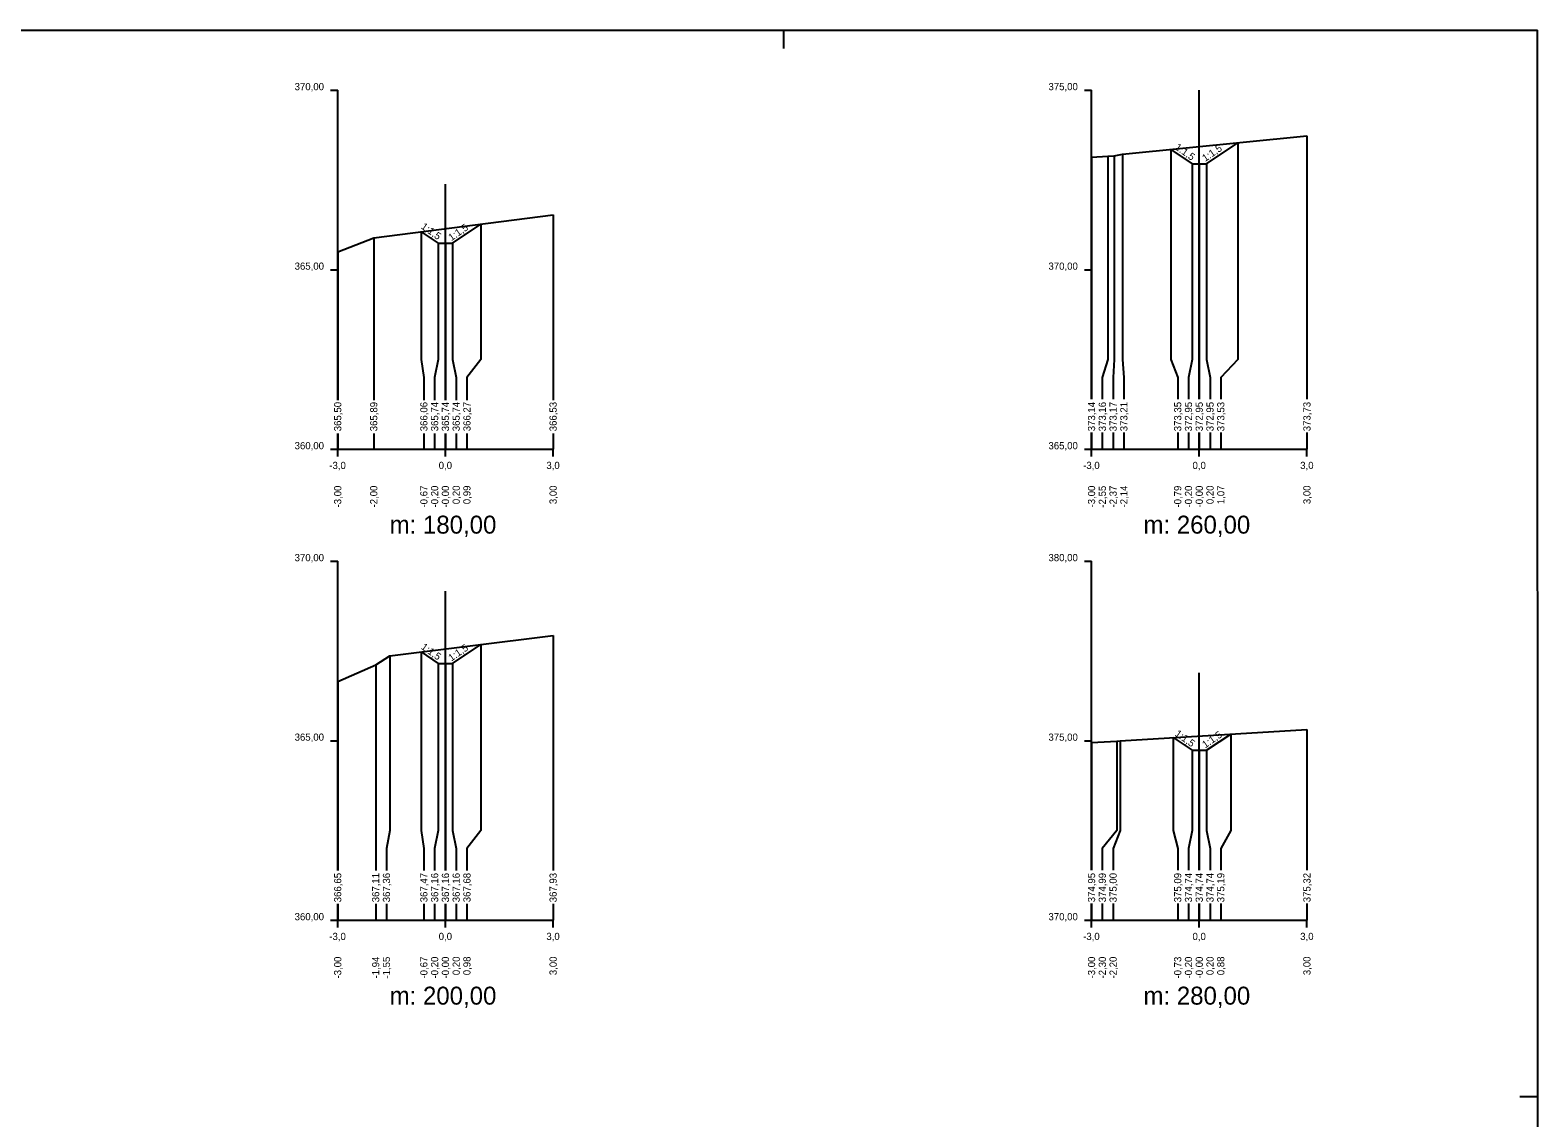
# Model space of a CAD drawing. Extents: x -497367.2 to -497283.2, y -1136708.7 to -1136649.3.
# Drawn here: x -497325.24 to -497283.24, y -1136679.63 to -1136649.33 of the extents above; entities that cross this region are included whole.
import ezdxf

# ---------------------------------------------------------------- set-up
doc = ezdxf.new("R2010")
doc.units = 0
for name, color, linetype in [('11', 7, 'Continuous'), ('16', 7, 'Continuous'), ('21', 7, 'Continuous'), ('28', 7, 'Continuous'), ('59', 7, 'Continuous'), ('8', 7, 'Continuous'), ('Vrstva 63', 7, 'Continuous')]:
    doc.layers.add(name, color=color, linetype=linetype)

msp = doc.modelspace()

# ---------------------------------------------------------------- linework, layer by layer
for points in [[(-497295.671, -1136652.867), (-497295.22, -1136652.847), (-497295.042, -1136652.833), (-497294.809, -1136652.792), (-497289.671, -1136652.279)], [(-497293.464, -1136652.658), (-497292.871, -1136653.053), (-497292.671, -1136653.053), (-497292.471, -1136653.053), (-497291.598, -1136652.472)], [(-497291.598, -1136652.473), (-497291.598, -1136652.472), (-497291.598, -1136652.471)], [(-497292.871, -1136653.054), (-497292.871, -1136653.053), (-497292.871, -1136653.052)], [(-497292.471, -1136653.054), (-497292.471, -1136653.053), (-497292.471, -1136653.052)], [(-497316.671, -1136655.507), (-497315.668, -1136655.115), (-497310.671, -1136654.48)], [(-497314.344, -1136654.946), (-497313.871, -1136655.262), (-497313.671, -1136655.262), (-497313.471, -1136655.262), (-497312.68, -1136654.735)], [(-497313.871, -1136655.263), (-497313.871, -1136655.262), (-497313.871, -1136655.261)], [(-497313.471, -1136655.263), (-497313.471, -1136655.262), (-497313.471, -1136655.261)], [(-497316.671, -1136667.479), (-497315.613, -1136667.015), (-497315.221, -1136666.762), (-497310.671, -1136666.198)], [(-497314.346, -1136666.653), (-497313.871, -1136666.97), (-497313.671, -1136666.97), (-497313.471, -1136666.97), (-497312.688, -1136666.448)], [(-497313.871, -1136666.971), (-497313.871, -1136666.97), (-497313.871, -1136666.969)], [(-497313.471, -1136666.971), (-497313.471, -1136666.97), (-497313.471, -1136666.969)], [(-497295.671, -1136669.172), (-497294.97, -1136669.134), (-497294.875, -1136669.128), (-497289.671, -1136668.808)], [(-497293.399, -1136669.037), (-497292.871, -1136669.389), (-497292.671, -1136669.389), (-497292.471, -1136669.389), (-497291.795, -1136668.939)], [(-497292.871, -1136669.39), (-497292.871, -1136669.389), (-497292.871, -1136669.388)], [(-497292.471, -1136669.39), (-497292.471, -1136669.389), (-497292.471, -1136669.388)]]:
    msp.add_lwpolyline(points)
at = {"layer": '11'}
for points in [[(-497291.598, -1136652.472), (-497291.598, -1136658.506), (-497292.071, -1136659.006), (-497292.071, -1136659.608)], [(-497289.671, -1136652.279), (-497289.671, -1136658.506), (-497289.671, -1136659.006), (-497289.671, -1136659.608)], [(-497295.671, -1136652.867), (-497295.671, -1136658.506), (-497295.671, -1136659.006), (-497295.671, -1136659.608)], [(-497295.22, -1136652.847), (-497295.22, -1136658.506), (-497295.371, -1136659.006), (-497295.371, -1136659.608)], [(-497295.042, -1136652.833), (-497295.042, -1136658.506), (-497295.071, -1136659.006), (-497295.071, -1136659.608)], [(-497294.809, -1136652.792), (-497294.809, -1136658.506), (-497294.771, -1136659.006), (-497294.771, -1136659.608)], [(-497293.464, -1136652.658), (-497293.464, -1136658.506), (-497293.271, -1136659.006), (-497293.271, -1136659.608)], [(-497292.871, -1136653.053), (-497292.871, -1136658.506), (-497292.971, -1136659.006), (-497292.971, -1136659.608)], [(-497292.671, -1136653.053), (-497292.671, -1136658.506), (-497292.671, -1136659.006), (-497292.671, -1136659.608)], [(-497292.471, -1136653.053), (-497292.471, -1136658.506), (-497292.371, -1136659.006), (-497292.371, -1136659.608)], [(-497310.671, -1136654.48), (-497310.671, -1136658.506), (-497310.671, -1136659.006), (-497310.671, -1136659.635)], [(-497315.668, -1136655.115), (-497315.668, -1136658.506), (-497315.668, -1136659.006), (-497315.668, -1136659.635)], [(-497314.344, -1136654.946), (-497314.344, -1136658.506), (-497314.271, -1136659.006), (-497314.271, -1136659.635)], [(-497312.68, -1136654.735), (-497312.68, -1136658.506), (-497313.071, -1136659.006), (-497313.071, -1136659.635)], [(-497316.671, -1136655.507), (-497316.671, -1136658.506), (-497316.671, -1136659.006), (-497316.671, -1136659.635)], [(-497313.871, -1136655.262), (-497313.871, -1136658.506), (-497313.971, -1136659.006), (-497313.971, -1136659.635)], [(-497313.671, -1136655.262), (-497313.671, -1136658.506), (-497313.671, -1136659.006), (-497313.671, -1136659.635)], [(-497313.471, -1136655.262), (-497313.471, -1136658.506), (-497313.371, -1136659.006), (-497313.371, -1136659.635)], [(-497316.671, -1136660.569), (-497316.671, -1136661.006)], [(-497315.668, -1136660.569), (-497315.668, -1136661.006)], [(-497314.271, -1136660.569), (-497314.271, -1136661.006)], [(-497313.971, -1136660.569), (-497313.971, -1136661.006)], [(-497313.671, -1136660.569), (-497313.671, -1136661.006)], [(-497313.371, -1136660.569), (-497313.371, -1136661.006)], [(-497313.071, -1136660.569), (-497313.071, -1136661.006)], [(-497310.671, -1136660.569), (-497310.671, -1136661.006)], [(-497295.671, -1136660.542), (-497295.671, -1136661.006)], [(-497295.371, -1136660.542), (-497295.371, -1136661.006)], [(-497295.071, -1136660.542), (-497295.071, -1136661.006)], [(-497294.771, -1136660.542), (-497294.771, -1136661.006)], [(-497293.271, -1136660.542), (-497293.271, -1136661.006)], [(-497292.971, -1136660.542), (-497292.971, -1136661.006)], [(-497292.671, -1136660.542), (-497292.671, -1136661.006)], [(-497292.371, -1136660.542), (-497292.371, -1136661.006)], [(-497292.071, -1136660.542), (-497292.071, -1136661.006)], [(-497289.671, -1136660.542), (-497289.671, -1136661.006)], [(-497312.688, -1136666.448), (-497312.688, -1136671.625), (-497313.071, -1136672.125), (-497313.071, -1136672.738)], [(-497310.671, -1136666.198), (-497310.671, -1136671.625), (-497310.671, -1136672.125), (-497310.671, -1136672.738)], [(-497315.221, -1136666.762), (-497315.221, -1136671.625), (-497315.313, -1136672.125), (-497315.313, -1136672.738)], [(-497314.346, -1136666.653), (-497314.346, -1136671.625), (-497314.271, -1136672.125), (-497314.271, -1136672.738)], [(-497315.613, -1136667.015), (-497315.613, -1136671.625), (-497315.613, -1136672.125), (-497315.613, -1136672.738)], [(-497313.871, -1136666.97), (-497313.871, -1136671.625), (-497313.971, -1136672.125), (-497313.971, -1136672.738)], [(-497313.671, -1136666.97), (-497313.671, -1136671.625), (-497313.671, -1136672.125), (-497313.671, -1136672.738)], [(-497313.471, -1136666.97), (-497313.471, -1136671.625), (-497313.371, -1136672.125), (-497313.371, -1136672.738)], [(-497316.671, -1136667.479), (-497316.671, -1136671.625), (-497316.671, -1136672.125), (-497316.671, -1136672.738)], [(-497291.795, -1136668.939), (-497291.795, -1136671.625), (-497292.071, -1136672.125), (-497292.071, -1136672.728)], [(-497289.671, -1136668.808), (-497289.671, -1136671.625), (-497289.671, -1136672.125), (-497289.671, -1136672.728)], [(-497295.671, -1136669.172), (-497295.671, -1136671.625), (-497295.671, -1136672.125), (-497295.671, -1136672.728)], [(-497294.97, -1136669.134), (-497294.97, -1136671.625), (-497295.371, -1136672.125), (-497295.371, -1136672.728)], [(-497294.875, -1136669.128), (-497294.875, -1136671.625), (-497295.071, -1136672.125), (-497295.071, -1136672.728)], [(-497293.399, -1136669.037), (-497293.399, -1136671.625), (-497293.271, -1136672.125), (-497293.271, -1136672.728)], [(-497292.871, -1136669.389), (-497292.871, -1136671.625), (-497292.971, -1136672.125), (-497292.971, -1136672.728)], [(-497292.671, -1136669.389), (-497292.671, -1136671.625), (-497292.671, -1136672.125), (-497292.671, -1136672.728)], [(-497292.471, -1136669.389), (-497292.471, -1136671.625), (-497292.371, -1136672.125), (-497292.371, -1136672.728)], [(-497316.671, -1136673.672), (-497316.671, -1136674.125)], [(-497315.613, -1136673.672), (-497315.613, -1136674.125)], [(-497315.313, -1136673.672), (-497315.313, -1136674.125)], [(-497314.271, -1136673.672), (-497314.271, -1136674.125)], [(-497313.971, -1136673.672), (-497313.971, -1136674.125)], [(-497313.671, -1136673.672), (-497313.671, -1136674.125)], [(-497313.371, -1136673.672), (-497313.371, -1136674.125)], [(-497313.071, -1136673.672), (-497313.071, -1136674.125)], [(-497310.671, -1136673.672), (-497310.671, -1136674.125)], [(-497295.671, -1136673.662), (-497295.671, -1136674.125)], [(-497295.371, -1136673.662), (-497295.371, -1136674.125)], [(-497295.071, -1136673.662), (-497295.071, -1136674.125)], [(-497293.271, -1136673.662), (-497293.271, -1136674.125)], [(-497292.971, -1136673.662), (-497292.971, -1136674.125)], [(-497292.671, -1136673.662), (-497292.671, -1136674.125)], [(-497292.371, -1136673.662), (-497292.371, -1136674.125)], [(-497292.071, -1136673.662), (-497292.071, -1136674.125)], [(-497289.671, -1136673.662), (-497289.671, -1136674.125)]]:
    msp.add_lwpolyline(points, dxfattribs=at)
at = {"layer": '16'}
for p, q in [((-497316.671, -1136661.006), (-497310.671, -1136661.006)), ((-497295.671, -1136661.006), (-497289.671, -1136661.006)), ((-497316.671, -1136674.125), (-497310.671, -1136674.125)), ((-497295.671, -1136674.125), (-497289.671, -1136674.125))]:
    msp.add_line(p, q, dxfattribs=at)
for points in [[(-497292.671, -1136653.054), (-497292.671, -1136653.053), (-497292.671, -1136653.052)], [(-497313.671, -1136655.262), (-497313.671, -1136655.262), (-497313.671, -1136655.261)], [(-497313.671, -1136666.971), (-497313.671, -1136666.97), (-497313.671, -1136666.969)], [(-497292.671, -1136669.39), (-497292.671, -1136669.389), (-497292.671, -1136669.388)]]:
    msp.add_lwpolyline(points, dxfattribs=at)
at = {"layer": '21'}
for p, q in [((-497316.871, -1136651.006), (-497316.671, -1136651.006)), ((-497295.871, -1136651.006), (-497295.671, -1136651.006)), ((-497316.871, -1136656.006), (-497316.671, -1136656.006)), ((-497295.871, -1136656.006), (-497295.671, -1136656.006)), ((-497316.871, -1136661.006), (-497316.671, -1136661.006)), ((-497295.871, -1136661.006), (-497295.671, -1136661.006)), ((-497316.871, -1136664.125), (-497316.671, -1136664.125)), ((-497295.871, -1136664.125), (-497295.671, -1136664.125)), ((-497316.871, -1136669.125), (-497316.671, -1136669.125)), ((-497295.871, -1136669.125), (-497295.671, -1136669.125)), ((-497316.871, -1136674.125), (-497316.671, -1136674.125)), ((-497295.871, -1136674.125), (-497295.671, -1136674.125))]:
    msp.add_line(p, q, dxfattribs=at)
at = {"layer": '28'}
for p, q in [((-497292.671, -1136659.608), (-497292.671, -1136651.006)), ((-497313.671, -1136659.635), (-497313.671, -1136653.627)), ((-497313.671, -1136661.006), (-497313.671, -1136660.569)), ((-497292.671, -1136661.006), (-497292.671, -1136660.542)), ((-497313.671, -1136672.738), (-497313.671, -1136664.955)), ((-497292.671, -1136672.728), (-497292.671, -1136667.233)), ((-497313.671, -1136674.125), (-497313.671, -1136673.672)), ((-497292.671, -1136674.125), (-497292.671, -1136673.662))]:
    msp.add_line(p, q, dxfattribs=at)
at = {"layer": '59'}
for p, q in [((-497316.671, -1136661.206), (-497316.671, -1136661.006)), ((-497313.671, -1136661.206), (-497313.671, -1136661.006)), ((-497310.671, -1136661.206), (-497310.671, -1136661.006)), ((-497295.671, -1136661.206), (-497295.671, -1136661.006)), ((-497292.671, -1136661.206), (-497292.671, -1136661.006)), ((-497289.671, -1136661.206), (-497289.671, -1136661.006)), ((-497316.671, -1136674.325), (-497316.671, -1136674.125)), ((-497313.671, -1136674.325), (-497313.671, -1136674.125)), ((-497310.671, -1136674.325), (-497310.671, -1136674.125)), ((-497295.671, -1136674.325), (-497295.671, -1136674.125)), ((-497292.671, -1136674.325), (-497292.671, -1136674.125)), ((-497289.671, -1136674.325), (-497289.671, -1136674.125))]:
    msp.add_line(p, q, dxfattribs=at)
at = {"layer": '8'}
for p, q in [((-497316.671, -1136659.635), (-497316.671, -1136651.006)), ((-497295.671, -1136659.608), (-497295.671, -1136651.006)), ((-497316.671, -1136661.006), (-497316.671, -1136660.569)), ((-497295.671, -1136661.006), (-497295.671, -1136660.542)), ((-497316.671, -1136672.738), (-497316.671, -1136664.125)), ((-497295.671, -1136672.728), (-497295.671, -1136664.125)), ((-497316.671, -1136674.125), (-497316.671, -1136673.672)), ((-497295.671, -1136674.125), (-497295.671, -1136673.662))]:
    msp.add_line(p, q, dxfattribs=at)
at = {"layer": 'Vrstva 63'}
for p, q in [((-497367.248, -1136649.335), (-497283.248, -1136649.333)), ((-497304.239, -1136649.84), (-497304.239, -1136649.337)), ((-497283.238, -1136708.735), (-497283.248, -1136649.333)), ((-497283.743, -1136679.034), (-497283.243, -1136679.034))]:
    msp.add_line(p, q, dxfattribs=at)

# ---------------------------------------------------------------- texts
at = {"layer": '16'}
for s, p in [('365,50', (-497316.571, -1136660.506)), ('365,89', (-497315.568, -1136660.506)), ('366,06', (-497314.171, -1136660.506)), ('365,74', (-497313.871, -1136660.506)), ('365,74', (-497313.571, -1136660.506)), ('365,74', (-497313.271, -1136660.506)), ('366,27', (-497312.971, -1136660.506)), ('366,53', (-497310.571, -1136660.506)), ('373,14', (-497295.571, -1136660.506)), ('373,16', (-497295.271, -1136660.506)), ('373,17', (-497294.971, -1136660.506)), ('373,21', (-497294.671, -1136660.506)), ('373,35', (-497293.171, -1136660.506)), ('372,95', (-497292.871, -1136660.506)), ('372,95', (-497292.571, -1136660.506)), ('372,95', (-497292.271, -1136660.506)), ('373,53', (-497291.971, -1136660.506)), ('373,73', (-497289.571, -1136660.506)), ('366,65', (-497316.571, -1136673.625)), ('367,11', (-497315.513, -1136673.625)), ('367,36', (-497315.213, -1136673.625)), ('367,47', (-497314.171, -1136673.625)), ('367,16', (-497313.871, -1136673.625)), ('367,16', (-497313.571, -1136673.625)), ('367,16', (-497313.271, -1136673.625)), ('367,68', (-497312.971, -1136673.625)), ('367,93', (-497310.571, -1136673.625)), ('374,95', (-497295.571, -1136673.625)), ('374,99', (-497295.271, -1136673.625)), ('375,00', (-497294.971, -1136673.625)), ('375,09', (-497293.171, -1136673.625)), ('374,74', (-497292.871, -1136673.625)), ('374,74', (-497292.571, -1136673.625)), ('374,74', (-497292.271, -1136673.625)), ('375,19', (-497291.971, -1136673.625)), ('375,32', (-497289.571, -1136673.625))]:
    msp.add_text(s, height=0.2, rotation=90, dxfattribs=at).set_placement(p)
at = {"layer": '21'}
for s, p in [('370,00', (-497317.871, -1136651.006)), ('375,00', (-497296.871, -1136651.006)), ('365,00', (-497317.871, -1136656.006)), ('370,00', (-497296.871, -1136656.006)), ('360,00', (-497317.871, -1136661.006)), ('365,00', (-497296.871, -1136661.006)), ('-3,0', (-497316.905, -1136661.556)), ('0,0', (-497313.858, -1136661.556)), ('3,0', (-497310.858, -1136661.556)), ('-3,0', (-497295.905, -1136661.556)), ('0,0', (-497292.858, -1136661.556)), ('3,0', (-497289.858, -1136661.556)), ('370,00', (-497317.871, -1136664.125)), ('380,00', (-497296.871, -1136664.125)), ('365,00', (-497317.871, -1136669.125)), ('375,00', (-497296.871, -1136669.125)), ('360,00', (-497317.871, -1136674.125)), ('370,00', (-497296.871, -1136674.125)), ('-3,0', (-497316.905, -1136674.675)), ('0,0', (-497313.858, -1136674.675)), ('3,0', (-497310.858, -1136674.675)), ('-3,0', (-497295.905, -1136674.675)), ('0,0', (-497292.858, -1136674.675)), ('3,0', (-497289.858, -1136674.675))]:
    msp.add_text(s, height=0.2, dxfattribs=at).set_placement(p)
for rotation, p in [(324.91, (-497293.367, -1136652.635)), (34.4489, (-497292.504, -1136653.005)), (324.91, (-497314.367, -1136654.843)), (34.4489, (-497313.504, -1136655.213)), (324.91, (-497314.367, -1136666.552)), (34.4489, (-497313.504, -1136666.921)), (324.91, (-497293.367, -1136668.971)), (34.4489, (-497292.504, -1136669.341))]:
    msp.add_text('1:1,5', height=0.2, rotation=rotation, dxfattribs=at).set_placement(p)
at = {"layer": '28'}
for s, p in [('m: 180,00', (-497315.224, -1136663.356)), ('m: 260,00', (-497294.224, -1136663.356)), ('m: 200,00', (-497315.224, -1136676.475)), ('m: 280,00', (-497294.224, -1136676.475))]:
    msp.add_text(s, height=0.5, dxfattribs=at).set_placement(p)
at = {"layer": '59'}
for s, p in [('-3,00', (-497316.571, -1136662.629)), ('-2,00', (-497315.568, -1136662.629)), ('-0,67', (-497314.171, -1136662.63)), ('-0,20', (-497313.871, -1136662.629)), ('-0,00', (-497313.571, -1136662.629)), ('0,20', (-497313.271, -1136662.536)), ('0,99', (-497312.971, -1136662.537)), ('3,00', (-497310.571, -1136662.536)), ('-3,00', (-497295.571, -1136662.629)), ('-2,55', (-497295.271, -1136662.632)), ('-2,37', (-497294.971, -1136662.63)), ('-2,14', (-497294.671, -1136662.629)), ('-0,79', (-497293.171, -1136662.63)), ('-0,20', (-497292.871, -1136662.629)), ('-0,00', (-497292.571, -1136662.629)), ('0,20', (-497292.271, -1136662.536)), ('1,07', (-497291.971, -1136662.537)), ('3,00', (-497289.571, -1136662.536)), ('-3,00', (-497316.571, -1136675.748)), ('-1,94', (-497315.513, -1136675.748)), ('-1,55', (-497315.213, -1136675.75)), ('-0,67', (-497314.171, -1136675.749)), ('-0,20', (-497313.871, -1136675.748)), ('-0,00', (-497313.571, -1136675.748)), ('0,20', (-497313.271, -1136675.655)), ('0,98', (-497312.971, -1136675.656)), ('3,00', (-497310.571, -1136675.655)), ('-3,00', (-497295.571, -1136675.748)), ('-2,30', (-497295.271, -1136675.748)), ('-2,20', (-497294.971, -1136675.748)), ('-0,73', (-497293.171, -1136675.749)), ('-0,20', (-497292.871, -1136675.748)), ('-0,00', (-497292.571, -1136675.748)), ('0,20', (-497292.271, -1136675.655)), ('0,88', (-497291.971, -1136675.656)), ('3,00', (-497289.571, -1136675.655))]:
    msp.add_text(s, height=0.2, rotation=90, dxfattribs=at).set_placement(p)

doc.saveas('drawing.dxf')
